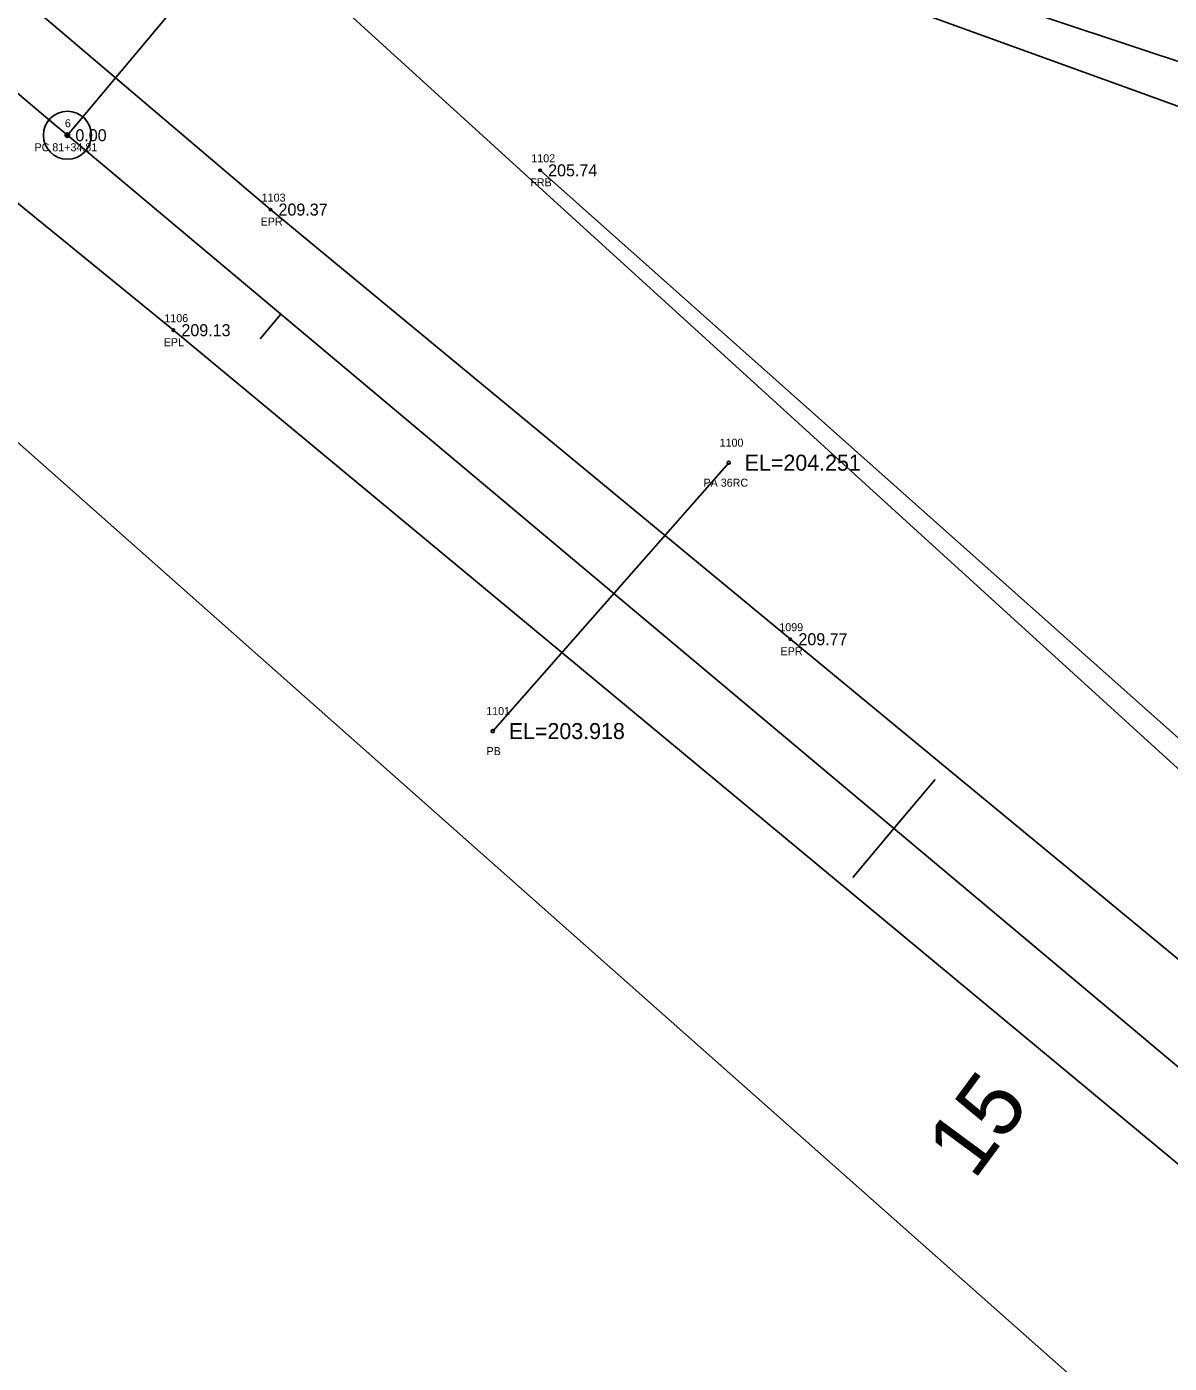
# Model space of a CAD drawing. Extents: x 2259948 to 2261336, y 1064647 to 1065986.
# Drawn here: x 2260584.5 to 2260727.2, y 1065109.7 to 1065276.7 of the extents above; entities that cross this region are included whole.
import ezdxf

# ---------------------------------------------------------------- set-up
doc = ezdxf.new("R2010")
doc.units = 0
for name, color, linetype in [('RD_EX_DR_Pipe', 7, 'Continuous'), ('RD_EX_DR_Pipe_txCode', 7, 'Continuous'), ('RD_EX_Fence_Other', 7, 'Continuous'), ('RD_EX_Fence_Other_txCode', 7, 'Continuous'), ('RD_EX_H2O', 7, 'Continuous'), ('RD_EX_Road', 7, 'Continuous'), ('RD_EX_Road_txCode', 7, 'Continuous'), ('RD_EX_TX_Fence_Other_ELEV', 7, 'Continuous'), ('RD_EX_TX_Road_ELEV', 7, 'Continuous'), ('RD_EX_VEG', 7, 'Continuous'), ('RD_HC_Cl', 7, 'Continuous'), ('RD_HC_Data', 7, 'Continuous'), ('RD_HC_Data_Tic', 7, 'Continuous'), ('RD_HC_Survey_ELEV', 7, 'Continuous'), ('RD_HC_TX_Sta50', 7, 'Continuous'), ('RD_HC_txCode', 7, 'Continuous'), ('RD_SMD_Locator', 7, 'Continuous'), ('RD_TX_Pipe_ElevEX', 7, 'Continuous')]:
    doc.layers.add(name, color=color, linetype=linetype)

msp = doc.modelspace()

# ---------------------------------------------------------------- linework, layer by layer
at = {"layer": 'RD_EX_DR_Pipe'}
msp.add_line((2260672.18, 1065222.21), (2260642.7, 1065188.67), dxfattribs=at)
at = {"layer": 'RD_EX_Fence_Other'}
msp.add_lwpolyline([(2260805.94, 1065129.03), (2260757.87, 1065161.54), (2260648.62, 1065258.75)], dxfattribs=at)
at = {"layer": 'RD_EX_H2O'}
msp.add_lwpolyline([(2260646.56, 1065296.38), (2260731.62, 1065265.57), (2260787.15, 1065228.1), (2260847.76, 1065200.44), (2260874.83, 1065172.21)], dxfattribs=at)
at = {"layer": 'RD_EX_Road'}
for points in [[(2260785.94, 1065112.1), (2260748.83, 1065143.25), (2260679.89, 1065200.15), (2260614.93, 1065253.84), (2260576.4, 1065286.6), (2260541.88, 1065316.4), (2260503.82, 1065350.69)], [(2260773.44, 1065097.37), (2260736.13, 1065128.07), (2260602.8, 1065238.77), (2260563.77, 1065270.54), (2260528.16, 1065301.97), (2260490.72, 1065336.18)]]:
    msp.add_lwpolyline(points, dxfattribs=at)
at = {"layer": 'RD_EX_VEG'}
for points in [[(2261134.31, 1064842.95), (2260842.2, 1065097.67), (2260806.91, 1065126.77), (2260758.4, 1065156.57), (2260401.57, 1065481.47), (2260414.95, 1065532.7)], [(2261105.29, 1064796.67), (2260883, 1064984.96), (2260766.14, 1065062.68), (2260367.33, 1065416.28), (2260257.33, 1065527.76)]]:
    msp.add_lwpolyline(points, dxfattribs=at)
at = {"layer": 'RD_HC_Cl'}
for p, q in [((2260647.64, 1065299.24), (2260736.83, 1065269.51)), ((2261118.79, 1064819.11), (2260589.55, 1065263.13))]:
    msp.add_line(p, q, dxfattribs=at)
msp.add_arc((2262430.9, 1067457.9), 2864.89, 227.26888, 230.00433, dxfattribs=at)
at = {"layer": 'RD_HC_Data'}
msp.add_line((2260589.55, 1065263.13), (2260664.14, 1065352.04), dxfattribs=at)
for radius in [3, 0.282]:
    msp.add_circle((2260589.55, 1065263.13), radius, dxfattribs=at)
at = {"layer": 'RD_HC_Data_Tic'}
for p, q in [((2260616.21, 1065240.76), (2260613.64, 1065237.7)), ((2260692.82, 1065176.49), (2260697.96, 1065182.62)), ((2260692.82, 1065176.49), (2260687.68, 1065170.36))]:
    msp.add_line(p, q, dxfattribs=at)
at = {"layer": 'RD_SMD_Locator'}
for centre, radius in [((2260589.55, 1065263.13), 0.15), ((2260648.62, 1065258.75), 0.15), ((2260614.93, 1065253.84), 0.15), ((2260602.8, 1065238.77), 0.15), ((2260672.18, 1065222.21), 0.2), ((2260679.89, 1065200.15), 0.15), ((2260642.7, 1065188.67), 0.2)]:
    msp.add_circle(centre, radius, dxfattribs=at)

# ---------------------------------------------------------------- texts
at = {"layer": 'RD_EX_DR_Pipe_txCode'}
for s, p in [('1100', (2260671.04, 1065224.21)), ('PA 36RC', (2260669.03, 1065219.21)), ('1101', (2260641.88, 1065190.67)), ('PB', (2260641.92, 1065185.67))]:
    msp.add_text(s, height=1, dxfattribs=at).set_placement(p)
at = {"layer": 'RD_EX_Fence_Other_txCode'}
for s, p in [('1102', (2260647.52, 1065259.75)), ('FRB', (2260647.39, 1065256.75))]:
    msp.add_text(s, height=1, dxfattribs=at).set_placement(p)
at = {"layer": 'RD_EX_Road_txCode'}
for s, p in [('1103', (2260613.83, 1065254.84)), ('EPR', (2260613.7, 1065251.84)), ('1106', (2260601.67, 1065239.77)), ('EPL', (2260601.59, 1065236.77)), ('1099', (2260678.5, 1065201.15)), ('EPR', (2260678.66, 1065198.15))]:
    msp.add_text(s, height=1, dxfattribs=at).set_placement(p)
at = {"layer": 'RD_EX_TX_Fence_Other_ELEV'}
msp.add_text('205.74', height=1.5, dxfattribs=at).set_placement((2260649.62, 1065258))
at = {"layer": 'RD_EX_TX_Road_ELEV'}
for s, p in [('209.37', (2260615.93, 1065253.09)), ('209.13', (2260603.8, 1065238.02)), ('209.77', (2260680.89, 1065199.4))]:
    msp.add_text(s, height=1.5, dxfattribs=at).set_placement(p)
at = {"layer": 'RD_HC_Survey_ELEV'}
msp.add_text('0.00', height=1.5, dxfattribs=at).set_placement((2260590.55, 1065262.38))
at = {"layer": 'RD_HC_TX_Sta50'}
msp.add_text('15', height=8, rotation=53.5303, dxfattribs=at).set_placement((2260702.83, 1065132.44))
at = {"layer": 'RD_HC_txCode'}
for s, p in [('6', (2260589.24, 1065264.13)), ('PC 81+34.81', (2260585.44, 1065261.13))]:
    msp.add_text(s, height=1, dxfattribs=at).set_placement(p)
at = {"layer": 'RD_TX_Pipe_ElevEX'}
for s, p in [('EL=204.251', (2260674.18, 1065221.21)), ('EL=203.918', (2260644.7, 1065187.67))]:
    msp.add_text(s, height=2, dxfattribs=at).set_placement(p)

doc.saveas('drawing.dxf')
